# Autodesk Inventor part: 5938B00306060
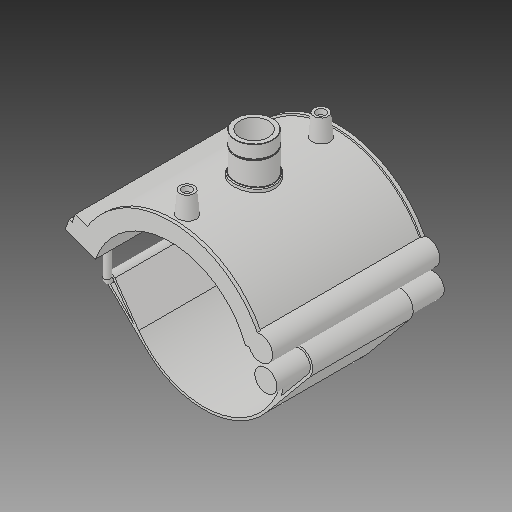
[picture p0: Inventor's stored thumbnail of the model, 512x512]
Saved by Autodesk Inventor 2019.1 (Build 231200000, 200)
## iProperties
Created: 2017-07
Part Number: 5938B00306060
Material: Generic
Description: PLASSON TRANSITION SADDLE 6''IPS x 1"NPT
Document SubType Name: Modeling
Designer: KIM
Density: 1 g/cm^3
Appearance: Default
Author: KIM
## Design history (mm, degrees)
derived "5938B.ipt"
feature "Solid1::5938B.ipt"
tag "TaggingFeature1"
body "Solid1"
other parameters: "d_" = 168, "B_" = 173.736, "H_" = 41.91, "L_" = 176.022, "d_t" = 6, "G_" = 30.291, "d148" = 2.52, "d160" = 2.52, "d169" = 2.52, "d192" = 6.72, "d0" = 168, "d1" = 201.6, "d2" = 434.34, "d3" = 42, "d4" = 176.022, "d5" = 0, "d40" = 104.832, "d41" = 42.4074, "d43" = 0, "d45" = 0, "d47" = 142.71, "d48" = 39.3783, "d50" = 0, "d78" = 122.8, "d79" = 15, "d80" = 70.4088, "d82" = 5 deg, "d84" = 4, "d85" = 14, "d86" = 0, "d87" = 3, "d88" = 0, "d96" = 205.632, "d97" = 3.52044, "d98" = 0, "d102" = 0.90873, "d103" = 30.291, "d104" = 25.146, "d105" = 0, "d106" = 24.2328, "d108" = 0, "d109" = -13.97, "d111" = 0.5, "d112" = 0.5, "d113" = 0, "d114" = 0.5, "d117" = 0.30291, "d120" = 140 deg, "d121" = 24.228, "d122" = 20 deg, "d123" = 806.4, "d124" = 120.96, "d126" = 0, "d143" = 173.04, "d145" = 25.84615, "d149" = 2.52, "d150" = 28.43077, "d153" = 176.022, "d154" = 0, "d156" = 100.8, "d157" = 160 deg, "d159" = 6.72, "d161" = 2.52, "d162" = 105.6132, "d163" = 0, "d164" = 84, "d167" = 16.8, "d168" = 98.34146, "d170" = 2.52, "d172" = 0, "d173" = 1, "d175" = 84, "d176" = 20 deg, "d177" = 11.76, "d178" = 33.6, "d180" = 0, "d183" = 13.44, "d184" = 9.408, "d185" = 57.20715, "d186" = 57.20715, "d187" = 100.8, "d188" = 10.08, "d189" = 11.76, "d190" = 0, "d191" = 120.96, "d193" = 6.72, "d194" = 3.444, "d195" = 90 deg, "d197" = 0, "d199" = 0
